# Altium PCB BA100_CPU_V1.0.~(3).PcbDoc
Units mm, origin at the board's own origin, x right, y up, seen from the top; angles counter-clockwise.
Board outline 152.4 x 101.6 mm, 2 copper layers (Top Layer, Bottom Layer); 85 components, 63 nets, 266 pads, 162 vias.
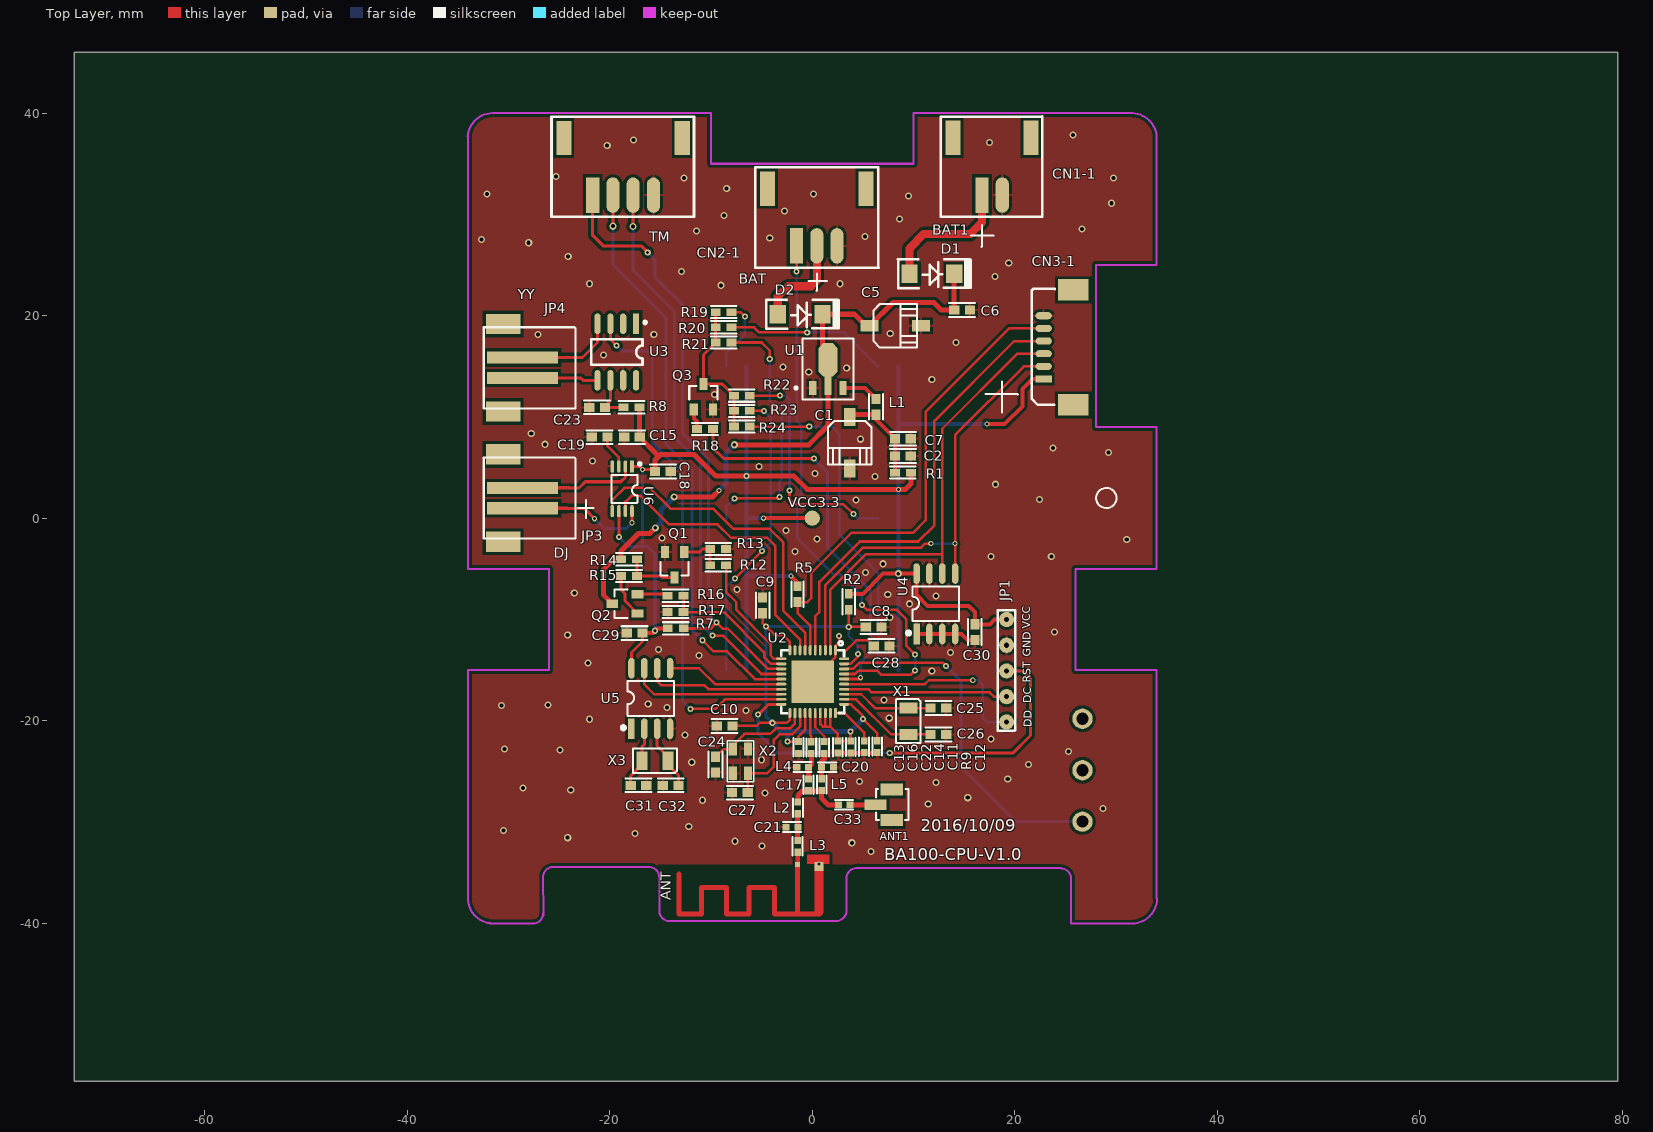
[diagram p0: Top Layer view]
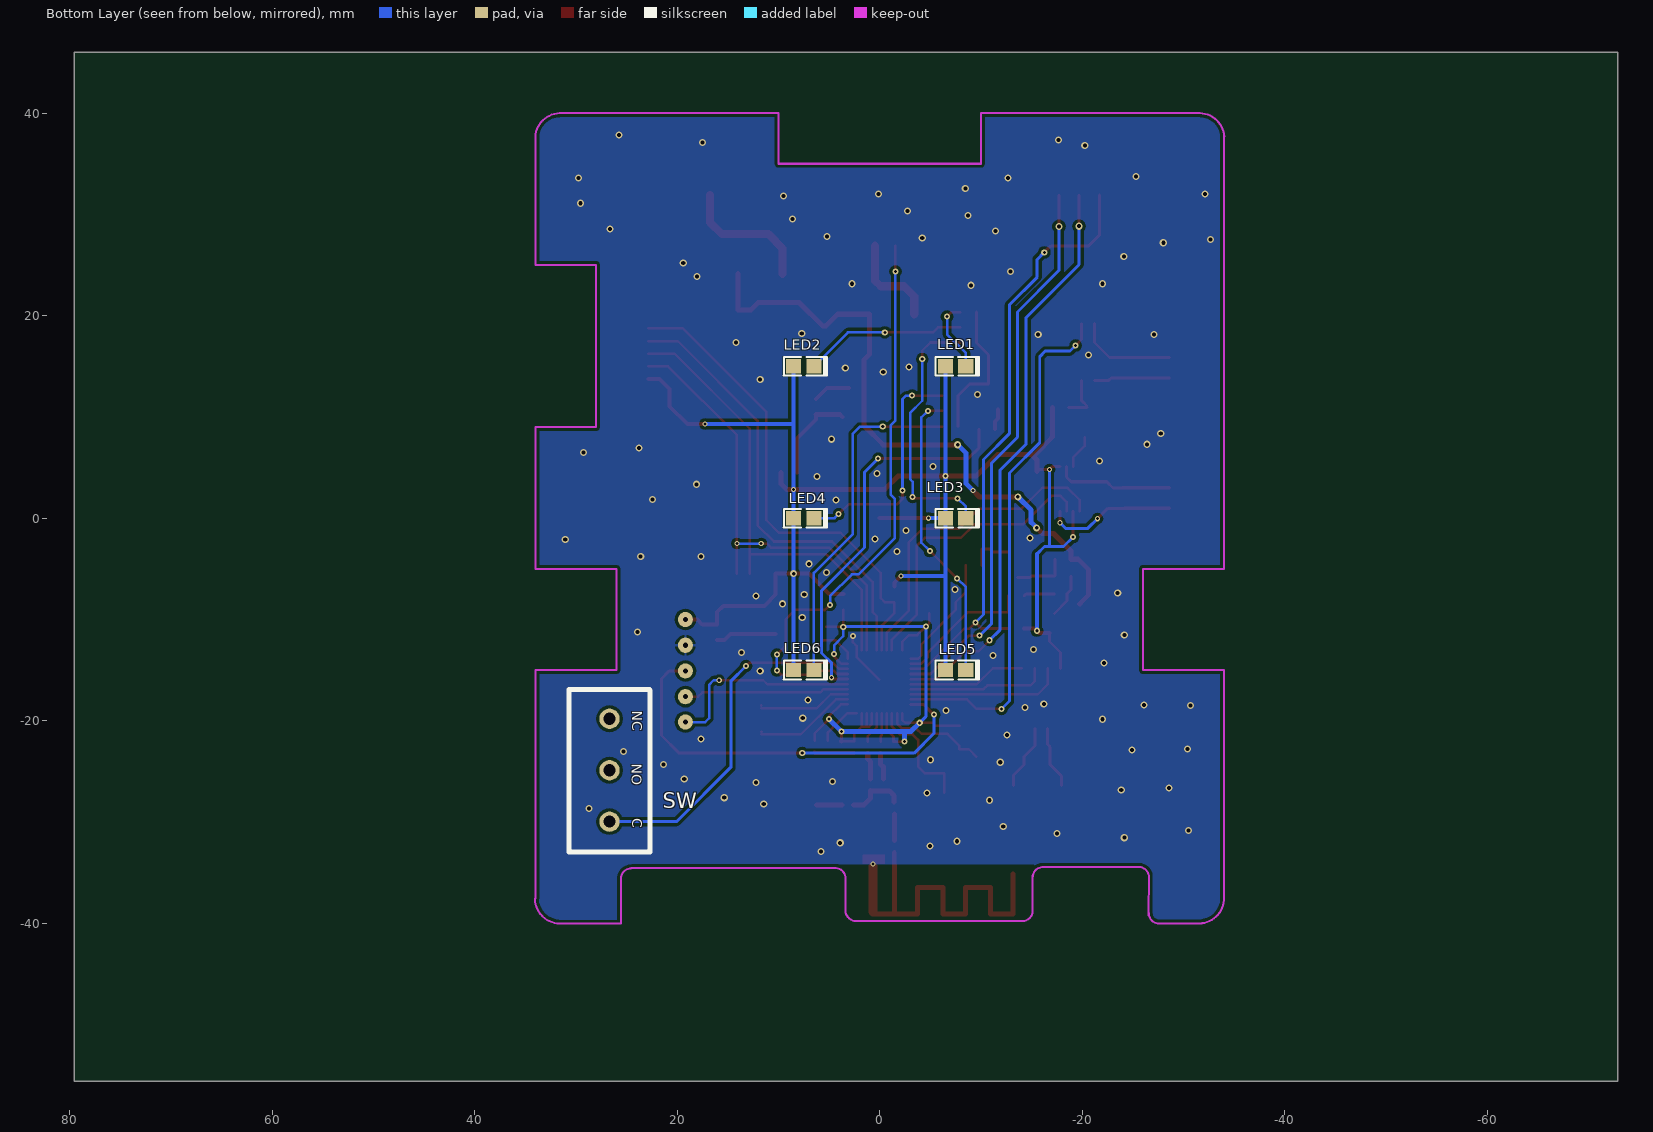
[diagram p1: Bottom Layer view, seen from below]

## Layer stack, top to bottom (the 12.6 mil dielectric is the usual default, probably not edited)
Top Solder: solder mask 0.0102, Solder Resist, Dk 3.5
Top Layer: signal copper 0.0356
Dielectric1: dielectric 0.32, FR-4, Dk 4.8
Bottom Layer: signal copper 0.0356
Bottom Solder: solder mask 0.0102, Solder Resist, Dk 3.5

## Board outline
-72.871,-55.595 79.529,-55.595 79.529,46.005 -72.871,46.005

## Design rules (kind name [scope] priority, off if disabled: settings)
Clearance [All] p1: gap=0.3
ComponentClearance [All] p1 off: gap=0.254 collisioncheckmode=3 verticalgap=0.254 showdistances=FALSE
FabricationTestPointUsage TestPointUsage [All] p1: valid=0 allowmultiple=FALSE
FabricationTestpoint Testpoint [All] p1: side=3 testpointundercomponent=TRUE minsize=1.016 maxsize=2.54 preferedsize=1.524 minholesize=0 maxholesize=1.016 preferedholesize=0.813 testpointgrid=0.025 allowsidetop=TRUE allowsidebottom=TRUE usegrid=TRUE gridtolerance=0
Height [All] p1 off: minheight=0 maxheight=25.4 prefheight=12.7
PlaneClearance [All] p1: clearance=0.3
PlaneConnect [All] p1: planeconnectstyle=Relief reliefexpansion=0.508 reliefentries=4 reliefconductorwidth=0.3 reliefairgap=0.3
PolygonConnect PolygonConnect_1 [IsVia] p1: connectstyle=Direct reliefconductorwidth=0.254 reliefentries=4 polygonreliefangle="90 Angle" airgapwidth=0.254
PolygonConnect [All] p2: connectstyle=Relief reliefconductorwidth=0.254 reliefentries=4 polygonreliefangle="90 Angle" airgapwidth=0.254
RoutingVias [All] p1: holewidth=0.4 width=0.7 viastyle="Through Hole" minholewidth=0.3 minwidth=0.5 maxholewidth=0.7 maxwidth=1.2
SolderMaskExpansion [All] p1: expansion=0.102
UnpouredPolygon [All] p1: allowunpoured=FALSE
Width [All] p1: maxlimit=1 minlimit=0.1 preferedwidth=0.3 minimp=50.000000 maximp=50.000000 favimp=50.000000
23 further rules are at their usual default settings.

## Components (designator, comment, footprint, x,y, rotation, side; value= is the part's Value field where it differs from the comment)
ANT "ANT" ANT -1.451,-34.185 r180 top
ANT1 "ANT" IPEX 6.25,-28.3 r180 top
C1 "10uf/16V,electro" ECAP_10U_4.3*4.3 3.7,7.45 r270 top
C2 "0.1uf" PC7-*****-KO-0A_0603_TDK 8.95,6.15 r180 top
C5 "10uf/16V,electro" ECAP_10U_4.3*4.3 8.2,19 r0 top
C6 "0.1uf" PC5-*****-**-0A_0603_TDK 14.8,20.55 r180 top
C7 "2.2uf" PC5-*****-**-0A_0603_TDK 8.95,7.85 r0 top
C8 "1uf" PC5-*****-**-0A_0603_TDK 6.05,-10.741 r0 top
C9 "0.1uf" PC7-*****-KO-0A_0603_TDK -4.9,-8.6 r90 top
C10 "0.1uf" PC5-*****-**-0A_0603_TDK -8.661,-20.515 r180 top
C11 "0.1uf" PC7-*****-KQA0A_0402_YAGEO 3.789,-22.596 r270 top
C12 "0.1uf" PC7-*****-KQA0A_0402_YAGEO 6.419,-22.555 r270 top
C13 "0.1uf" PC7-*****-KQA0A_0402_YAGEO -1.361,-22.635 r270 top
C14 "220pf" PC7-*****-KQA0A_0402_YAGEO 2.52,-22.596 r90 top
C15 "1uf" PC5-*****-**-0A_0603_TDK -17.8,8 r0 top
C16 "18p" PC7-*****-KQA0A_0402_YAGEO -0.091,-22.655 r270 top
C17 "1p" PC7-*****-KQA0A_0402_YAGEO -0.371,-26.335 r270 top
C18 "0.1uf" PC5-*****-**-0A_0603_TDK -14.75,4.6 r180 top
C19 "1uf" PC5-*****-**-0A_0603_TDK -21,8 r0 top
C20 "1p" PC7-*****-KQA0A_0402_YAGEO 1.5,-24.6 r0 top
C21 "1p" PC7-*****-KQA0A_0402_YAGEO -2,-30.5 r0 top
C22 "18p" PC7-*****-KQA0A_0402_YAGEO 1.179,-22.645 r270 top
C23 "1uf" PC5-*****-**-0A_0603_TDK -21.25,10.95 r180 top
C24 "27p" PC7-*****-KO-0A_0603_TDK -9.551,-24.335 r90 top
C25 "15P" PC5-*****-**-0A_0603_TDK 12.45,-18.745 r180 top
C26 "15P" PC7-*****-KO-0A_0603_TDK 12.45,-21.35 r180 top
C27 "27p" PC7-*****-KO-0A_0603_TDK -7.15,-27.1 r0 top
C28 "1uf" PC5-*****-**-0A_0603_TDK 6.85,-12.6 r180 top
C29 "0.1uf" PC7-*****-KO-0A_0603_TDK -17.55,-11.35 r180 top
C30 "0.1uf" PC5-*****-**-0A_0603_TDK 16.05,-11.25 r90 top
C31 "15P" PC7-*****-KO-0A_0603_TDK -17.161,-26.375 r0 top
C32 "15P" PC7-*****-KO-0A_0603_TDK -13.981,-26.375 r180 top
C33 "20P" PC7-*****-KQA0A_0402_YAGEO 3.15,-28.3 r0 top
CN1-1 "CN1" PH2.0-2PIN-SMT 16.75,31.9 r0 top
CN2-1 "CN2" PH2.0-3PIN-SMT -1.55,26.9 r0 top
CN3-1 "touch" PH1.25-6PIN-SMT 22.849,13.745 r90 top
D1 "SS12" SS12-DIDEO 9.6,24.15 r0 top
D2 "SS12" SS12-DIDEO -3.4,20.15 r0 top
JP1 "debugger" ISCP-5PIN 19.189,-10.005 r270 top
JP3 "SIP2" PH2.0-2PIN-LSMT1 -28.611,1.985 r270 top
JP4 "SIP2" PH2.0-2PIN-LSMT1 -28.611,14.855 r270 top
L1 "BLM18HG102SN1" PC7-*****-KO-0A_0603_TDK 6.3,11 r270 top
L2 "1nH" PC5-*****-**-0A_0402_TDK -1.421,-28.6 r270 top
L3 "3nH" PC5-*****-**-0A_0402_TDK -1.451,-32.405 r270 top
L4 "2nH" PC5-*****-**-0A_0402_TDK -0.951,-24.575 r0 top
L5 "2nH" PC5-*****-**-0A_0402_TDK 0.929,-26.305 r270 top
LED1 "MA2X335" LED-0805 -7.5,15 r180 bottom locked
LED2 "MA2X335" LED-0805 7.5,15 r180 bottom locked
LED3 "MA2X335" LED-0805 -7.5,0 r180 bottom locked
LED4 "MA2X335" LED-0805 7.5,0 r180 bottom locked
LED5 "MA2X335" LED-0805 -7.5,-15 r180 bottom locked
LED6 "MA2X335" LED-0805 7.5,-15 r180 bottom locked
Q1 "BC847B" PTR-C0025-00-2A_2SC1623 -13.6,-4.6 r180 top
Q2 "BC857B" PTR-C0025-00-2A_2SC1623 -18.5,-8.45 r90 top
Q3 "SS8050" PTR-C0025-00-2A_2SC1623 -10.75,12 r0 top
R1 "0ohm" PRC-*****-AM-0A_0603 8.95,4.5 r0 top
R2 "0ohm" PRC-*****-AM-0A_0603 3.6,-8.25 r90 top
R5 "10k" PRC-*****-AM-0A_0603 -1.45,-7.5 r270 top
R7 "10k" PRC-*****-AM-0A_0603 -13.481,-10.875 r0 top
R8 "0ohm" PRC-*****-AM-0A_0603 -17.85,10.95 r0 top
R9 "56k" PRC-*****-BM-0A_0402 5.112,-22.569 r270 top
R12 "4.7K" PRC-*****-AM-0A_0603 -9.3,-4.65 r180 top
R13 "100K" PRC-*****-AM-0A_0603 -9.3,-3.05 r180 top
R14 "47K" PRC-*****-AM-0A_0603 -18.1,-4.05 r180 top
R15 "30K" PRC-*****-AM-0A_0603 -18.1,-5.7 r180 top
R16 "75K" PRC-*****-AM-0A_0603 -13.5,-7.65 r180 top
R17 "20K" PRC-*****-AM-0A_0603 -13.501,-9.265 r0 top
R18 "2.7K" PRC-*****-AM-0A_0603 -10.6,8.8 r180 top
R19 "560" PRC-*****-AM-0A_0603 -8.75,20.35 r180 top
R20 "560" PRC-*****-AM-0A_0603 -8.75,18.85 r180 top
R21 "560" PRC-*****-AM-0A_0603 -8.75,17.35 r180 top
R22 "560" PRC-*****-AM-0A_0603 -6.95,12.1 r180 top
R23 "560" PRC-*****-AM-0A_0603 -6.95,10.6 r180 top
R24 "560" PRC-*****-AM-0A_0603 -6.95,9.05 r180 top
SW "SW-weidong" SW-weidong 26.679,-24.885 r90 bottom
TM "TM" PH2.0-4PIN-SMT -21.681,31.905 r0 top (schematic designator JP2)
U1 "HT7333" SOT89 1.55,14.25 r0 top
U2 "CC2541" CC2530_QFN40 2.3,-13.05 r270 top
U3 "NVC080C" SOP-8 -17.4,19.2 r270 top
U4 "AT24C64N" PIC-00570-40-2A_93LC46B 12.2,-8.45 r90 top
U5 "DS1302Z" PIC-00570-40-2A_93LC46B -15.95,-17.8 r90 top
U6 "PT5102" PT5102 -17.8,5.1 r270 top
X1 "32.768KHZ,F=12.5P" FC-135 9.489,-20.045 r270 top
X2 "CY_3225" CY_3225 -7.421,-25.095 r90 top
X3 "32.768KHZ,F=6P" FC-135 -15.531,-23.955 r180 top

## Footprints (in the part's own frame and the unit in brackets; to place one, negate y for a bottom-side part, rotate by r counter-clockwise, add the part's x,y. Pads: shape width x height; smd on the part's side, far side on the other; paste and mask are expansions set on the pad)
ANT [mm]
  rect 0.5x0.5 smd: 1(0,0)
  rect 0.9x0.9 smd: 2(-2.1,0.2)
  Top Layer lines w0.5: 11.7,0.96 11.7,4.9 9.5,4.9 9.5,2.26 7,2.26 7,4.9 4.8,4.9 4.8,2.26 2.3,2.26 2.3,4.9 0,4.9 ; 0,0 0,4.9 ; -2.26,4.79 -2.21,4.84 -2.15,4.9 0,4.9
  Top Layer lines w0.9: -2.1,4.65 -2.1,0.2
CC2530_QFN40 [mm]
  oval 1x0.28 smd: 1(-0.011,-0.009) 2(-0.011,-0.509) 3(-0.011,-1.009) 4(-0.011,-1.509) 5(-0.011,-2.009) 6(-0.011,-2.509) 7(-0.011,-3.009) 8(-0.011,-3.509) 9(-0.011,-4.009) 10(-0.011,-4.509) 21(6.189,-4.509) 22(6.189,-4.009) 23(6.189,-3.509) 24(6.189,-3.009) 25(6.189,-2.509) 26(6.189,-2.009) 27(6.189,-1.509) 28(6.189,-1.009) 29(6.189,-0.509) 30(6.189,-0.009)
  oval 0.28x1 smd: 11(0.832,-5.359) 12(1.332,-5.359) 13(1.832,-5.359) 14(2.332,-5.359) 15(2.832,-5.359) 16(3.332,-5.359) 17(3.832,-5.359) 18(4.332,-5.359) 19(4.832,-5.359) 20(5.332,-5.359) 31(5.332,0.841) 32(4.832,0.841) 33(4.332,0.841) 34(3.832,0.841) 35(3.332,0.841) 36(2.832,0.841) 37(2.332,0.841) 38(1.832,0.841) 39(1.332,0.841) 40(0.832,0.841)
  rect 4.2x4.2 smd: 41(3.089,-2.259)
  silkscreen extent -0.91,-5.37 6.21,0.85
CY_3225 [mm]
  round 0.5 on Top Overlay: 0(-0.64,-2.06)
  rect 1.3x0.8 smd: 1(-0.095,-1.07) 2(2.293,-1.07) 3(2.293,0.428) 4(-0.095,0.428)
  silkscreen extent -0.91,-1.63 3.11,0.99
ECAP_10U_4.3*4.3 [mm]
  rect 1.8x1.1 smd: 1(2.54,0) 2(-2.54,0)
  silkscreen extent -2.15,-2.15 2.15,2.15
FC-135 [mm]
  rect 1.1x1.8 smd: 1(-1.3,0) 2(1.3,0)
  silkscreen extent -2.17,-1.2 2.15,1.19
IPEX [mm]
  rect 2.2x1 smd: 1(0,0)
  rect 2.2x1.2 smd: 2(-1.6,-1.5) 3(-1.6,1.49)
  silkscreen extent -3.24,-1.56 -0.05,1.51
ISCP-5PIN [mm]
  round 1.5 hole 0.5: 1(0,0) 2(2.54,0) 3(5.07,0) 4(7.62,0) 5(10.12,0)
  silkscreen extent -0.93,-0.89 11,0.84
LED-0805 [mm]
  rect 1.5x1.4 smd: A(-1,0) C(1,0)
  silkscreen extent -1.98,-0.93 2.28,0.93
PC5-*****-**-0A_0402_TDK [mm] "0402"
  rect 0.7x0.65 smd: 1(-0.58,0) 2(0.58,0)
  silkscreen extent -0.91,-0.48 0.89,0.48
PC5-*****-**-0A_0603_TDK [mm] "0603"
  rect 1.016x0.9 smd: 1(-0.775,0) 2(0.776,0)
  silkscreen extent -1.28,-0.68 1.28,0.68
PC7-*****-KO-0A_0603_TDK [mm] "0603"
  rect 1.016x0.9 smd: 1(-0.776,0) 2(0.776,0)
  silkscreen extent -1.28,-0.68 1.28,0.68
PC7-*****-KQA0A_0402_YAGEO [mm] "0402"
  rect 0.7x0.65 smd: 1(-0.58,0) 2(0.58,0)
  silkscreen extent -0.91,-0.48 0.89,0.48
PH1.25-6PIN-SMT [mm]
  rect 0.7x1.6 smd: 1(0,0)
  oval 0.7x1.6 smd: 2(1.25,0) 3(2.5,0) 4(3.75,0) 5(5,0) 6(6.25,0)
  rect 2.1x3 smd: 7(-2.55,-2.91) 8(8.8,-2.91)
  silkscreen extent -2.54,-1.11 8.89,1.18
PH2.0-2PIN-LSMT1 [mm]
  rect 1.2x7 smd: 1(-1.005,0) 2(1.005,0)
  rect 2x3.4 smd: 3(-4.318,-1.905) 4(4.318,-1.905)
  silkscreen extent -4,-3.84 4,5.24
PH2.0-2PIN-SMT [mm]
  rect 1.3x3.5 smd: 1(0.01,0.01)
  oval 1.3x3.5 smd: 2(2.01,0.01)
  rect 1.5x3.4 smd: 3(-2.85,5.65) 4(4.85,5.65)
  silkscreen extent -4.06,-2.15 5.98,7.8
PH2.0-3PIN-SMT [mm]
  rect 1.3x3.5 smd: 1(0,0)
  oval 1.3x3.5 smd: 2(2,0) 3(3.99,-0.01)
  rect 1.5x3.4 smd: 4(-2.86,5.64) 5(6.85,5.64)
  silkscreen extent -4.07,-2.17 8.1,7.75
PH2.0-4PIN-SMT [mm]
  rect 1.3x3.5 smd: 1(0,0)
  oval 1.3x3.5 smd: 2(2,0) 3(3.99,-0.01) 4(6,-0.01)
  rect 1.5x3.4 smd: 5(-2.85,5.64) 6(8.85,5.64)
  silkscreen extent -4.07,-2.16 10,7.75
PIC-00570-40-2A_93LC46B [mil] "SOIC-8"
  rect 80x25 smd: 1(-117.5,75)
  oval 80x25 smd: 2(-117.5,25) 3(-117.5,-25) 4(-117.5,-75) 5(117.5,-75) 6(117.5,-25) 7(117.5,25) 8(117.5,75)
  silkscreen extent -119,-90 67,111
PRC-*****-AM-0A_0603 [mm] "0603"
  rect 0.966x0.762 smd: 1(-0.785,0) 2(0.785,0)
  silkscreen extent -1.26,-0.6 1.27,0.6
PRC-*****-BM-0A_0402 [mm] "0402"
  rect 0.7x0.65 smd: 1(-0.58,0) 2(0.58,0)
  silkscreen extent -0.91,-0.48 0.89,0.48
PT5102 [mm]
  rect 1.2x0.35 smd: 1(0,0)
  oval 1.2x0.35 smd: 2(-0.006,-0.65) 3(-0.006,-1.3) 4(-0.006,-1.95) 5(4.4,-1.95) 6(4.4,-1.3) 7(4.4,-0.65) 8(4.4,0)
  silkscreen extent -0.38,-2.03 3.58,0.89
PTR-C0025-00-2A_2SC1623 [mm]
  rect 0.816x1.174 smd: B(-0.95,-1.25) C(0,1.251) E(0.95,-1.25)
  silkscreen extent -1.4,-0.26 1.4,1.04
SOP-8 [mil]
  rect 80x24 smd: 1(0,0)
  oval 80x24 smd: 2(0,-50) 3(0,-100) 4(0,-150) 5(220,-150) 6(220,-100) 7(220,-50) 8(220,0)
  silkscreen extent -10,-175 160,40
SOT89 [mm] "SOT-89; Body 4.6 x 4.25 mm, inc. leads (LxW max)"
  oct 1.9x3.3 smd: 0(0,1.388)
  rect 0.7x1.35 smd: 1(-1.5,-1.388) 3(1.5,-1.388)
  rect 0.7x1.8 smd: 2(0,-1.162)
  silkscreen extent -3.27,-2.51 2.5,3.49
SS12-DIDEO [mm]
  rect 1.6x1.8 smd: 1(4.41,-0.01) 2(-0.01,-0.01)
  silkscreen extent -1.14,-1.43 6.03,1.44
SW-weidong [mm]
  round 2 hole 1.2: 1(-5.08,0) 2(0,0) 3(5.08,0)
  silkscreen extent -8.08,-4.01 7.95,4.01

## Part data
C1 C2 C5 C6 C7 C8 C9 C10 C11 C12 C13 C14 C15 C16 C17 C18 C19 C20 C21 C22 C23 C24 C25 C26 C27 C28 C29 C30 C31 C32 C33: library part PC7_0402_YAGEO, "PC7-*****-KQA0A"
CN1-1 JP3 JP4: library part CON2, "Connector"
CN2-1: library part JP1_E524.03
CN3-1: library part CON6
D1 D2: library part PDD_SD101CWS, "PDD-00330-00-2A"
JP1: library part CON5
L1 L2 L3 L4 L5: library part PWL_18nH, "PWL-00195-00-20"
LED1 LED2 LED3 LED4 LED5 LED6: library part PDD_MA2X335, "LED"
Q1: library part PTR_2SC3356, "PTR-C0028-00-2A"
Q2: library part PTR-PNP
Q3: library part PTR_2SC5344SF-Y, "PTR-C0230-00-20**"
R1 R2 R5 R7 R8 R9 R12 R13 R14 R15 R16 R17 R18: library part PRC_0603, "PRC-*****-AM-0A_0603"
R19 R20 R21 R22 R23 R24: library part RES
TM: library part "HDR1X4 ***"
U1: library part LM117K
U3: library part NV040C
U5: library part DS1302
U6: library part Component_1_1
X1: library part CRYSTAL, "Crystal"
X3: library part PTR_16MHZ, "PTR-X0320-20-2A"

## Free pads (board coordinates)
  round 1.5 smd: 0(0,0)

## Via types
v1: diameter 0.7, hole 0.4, Top Layer to Bottom Layer, 108 vias
v2: diameter 0.6, hole 0.3, Top Layer to Bottom Layer, 37 vias
v3: diameter 0.508, hole 0.3, Top Layer to Bottom Layer, 13 vias
v4: diameter 0.7, hole 0.35, Top Layer to Bottom Layer, 4 vias

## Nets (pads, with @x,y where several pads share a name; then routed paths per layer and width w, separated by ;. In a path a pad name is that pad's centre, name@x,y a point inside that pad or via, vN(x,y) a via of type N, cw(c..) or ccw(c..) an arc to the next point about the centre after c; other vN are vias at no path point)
AD: R16.1 R17.2 U2.12 | length 13.6
  Top Layer w0.25: R16.1@-12.696,-7.665 -12.696,-9.245 R17.2 -8.735,-9.265 -4.75,-13.25 -4.75,-13.7 -4.068,-14.382 U2.12
DC: JP1.4 U2.34 | length 16.4
  Top Layer w0.25: U2.34 5.532,-16.882 5.85,-17.2 17.5,-17.2 17.925,-17.625 JP1.4
DD: JP1.5 U2.35 | length 19.8
  Top Layer w0.25: U2.35 11.118,-16.382 11.5,-16 v3(15.85,-16)
  Bottom Layer w0.25: v3(15.85,-16) 16.4,-16 16.85,-16.45 16.85,-19.75 17.225,-20.125 JP1.5
DJ1: U2.7 U6.5 | length 32.3
  Top Layer w0.25: U6.5 -19.75,1.8 -18.55,3 -16.05,3 -14,0.95 -9.8,0.95 -7.8,-1.05 -4.2,-1.05 -2.85,-2.4 -2.85,-9.15 -0.709,-11.291 U2.7
DJ2: U2.8 U6.7 | length 29.3
  Top Layer w0.25: U6.7 -18.45,1.6 -17.85,2.2 -16.95,2.2 -14.15,-0.6 -9.35,-0.6 -8,-1.95 -4.45,-1.95 -3.65,-2.75 -3.65,-9.55 -1.209,-11.991 U2.8
GND: C1.1 C2.1 C5.1 C6.1 C7.2 C8.2 C9.2 C10.2 C11.2 C12.2 C13.2 C14.1 C15.1 C18.1 C19.1 C20.2 C21.1 C23.2 C24.1 C25.1 C26.1 C27.1 C28.1 C29.2 C30.1 C31.2 C32.2 CN1-1.2 CN2-1.3 CN3-1.6 JP1.2 L4.1 Q1.E Q3.E R9.2 R13.1 R17.1 TM.4 U1.1 U2.1 U2.41 U3.7 U4.1 U4.2 U4.3 U4.4 U4.7 U5.4 U6.4 X2.2 X2.4 | length 15.3
  Top Layer w0.25: U2.41@0.041,-15.959 2.291,-13.709 U2.1 2.291,-12.609 2.65,-12.25 v2(2.65,-11.65)
  Top Layer w0.4: C14.1 6.378,-23.176 C12.2 ; U4.1 U4.2 U4.3 U4.4 14.735,-11.435 15.325,-12.025 C30.1
  other v1: 5.8,-32.9 -4.95,-32.35 3.9,-32.05 -7.65,-31.9 -24.15,-31.55 -17.5,-31.15 -30.5,-30.85 -12.2,-30.45 28.7,-28.65 11.45,-28.2 -10.85,-27.85 15.35,-27.6 -4.65,-27.15 -23.85,-26.85 -28.55,-26.65 12.2,-26.1 4.65,-26 19.3,-25.75 21.35,-24.3 -11.9,-24.1 -5,-23.85 25.3,-23.05 -24.9,-22.9 -30.4,-22.8 17.65,-21.8 -12.55,-21.4 -22,-19.85 7.6,-19.75 -6.55,-19 -14.35,-18.7 -30.7,-18.5 -26.1,-18.45 -16.2,-18.35 7.1,-17.95 11.8,-15.1 -22.15,-14.3 -11.2,-13.55 13.65,-13.25 -15.2,-12.95 -24.15,-11.55 23.9,-11.25 7.65,-9.8 9.6,-8.45 12.2,-7.7 7.45,-7.55 -23.5,-7.4 -7.45,-7.05 5.25,-5.35 7,-4.5 17.65,-3.8 23.6,-3.8 -1.7,-3.3 31.05,-2.1 0.45,-2.05 -14.85,-1.95 -2.6,-1.2 4.3,1.8 22.45,1.85 18.1,3.35 6.2,4.1 0.25,4.4 -5.25,5.1 -21.7,5.65 29.25,6.5 23.75,6.95 -26.4,7.3 4.75,7.8 -27.75,8.35 -9.65,12.2 11.8,13.7 -0.35,14.45 3.4,14.85 -2.9,14.95 -20.6,16.1 14.2,17.35 -27.1,18.15 -15.65,18.15 7.7,18.25 -9,23 -22,23.15 2.75,23.15 18.05,23.85 -12.9,24.35 19.4,25.2 -24.1,25.85 -28,27.2 -32.65,27.5 -4.2,27.65 5.2,27.8 -11.45,28.35 26.65,28.55 8.6,29.55 -8.7,29.9 -2.75,30.35 29.55,31.1 9.5,31.8 -32.1,32 0.1,32 -8.45,32.55 -12.65,33.6 29.75,33.6 -25.3,33.75 -20.25,36.8 17.5,37.1 -17.65,37.35 25.75,37.85
  other v3: 0.65,-34.15
HI: CN3-1.5 R5.2 U2.6 | length 48.4
  Top Layer w0.25: R5.2@-1.45,-8.335 -1.45,-9.35 -0.209,-10.591 U2.6 ; R5.2 -0.485,-8.285 -0.1,-7.9 -0.1,-5.4 3.85,-1.45 9.95,-1.45 11.2,-0.2 11.2,10.5 19.445,18.745 CN3-1.5
LED_BACK: R18.1 U2.36 | length 38.3
  Top Layer w0.3: R18.1 -9.815,6.965 -8.75,5.9 v2(0.15,5.9) ; U2.36 4.618,-15.882 v3(4.75,-15.75)
  Bottom Layer w0.3: v2(0.15,5.9) 1.5,4.55 1.5,-2.9 5.75,-7.15 5.75,-13.3 4.75,-14.3 v3(4.75,-15.75)
NetANT1_1: ANT1.1 C33.2 | length 2.5
  Top Layer w0.5: C33.2 ANT1.1
NetANT_1: ANT.1 L3.2 | length 1.2
  Top Layer w0.45: ANT.1 L3.2
NetC1_2: C1.2 C2.2 C7.1 L1.2 R1.1 | length 9.2
  Top Layer w0.3: R1.1 R1.1@8.175,4.51
  Top Layer w0.4: C1.2 C1.2@3.935,10.225 ; L1.2 6.3,9.725 C7.1 R1.1@8.175,4.51
  Top Layer w0.5: C1.2@3.935,10.225 L1.2
NetC8_1: C8.1 C9.1 C10.1 C11.1 C12.1 C13.1 C14.2 R2.1 U2.10 U2.21 U2.24 U2.27 U2.28 U2.29 U2.31 U2.39 | length 67.4
  Top Layer w0.25: C10.1 -5.515,-20.515 -5.2,-20.2 v2(-3.95,-20.2) -2.5,-20.2 -2.209,-19.909 U2.21 ; C9.1 -4.9,-10.35 v2(-4.55,-10.7) -3.7,-11.55 -2.9,-11.55 -2.209,-12.241 U2.10 ; v2(-2.45,-22.055) C13.1 ; C13.1@-1.459,-21.956 C13.1 ; U2.24 -0.709,-20.909 -1.361,-21.561 C13.1 ; U2.27 0.791,-20.341 1.041,-20.591 1.291,-20.591 ; U2.28 1.291,-20.591 ; U2.29 1.791,-20.509 1.709,-20.591 ; U2.31 3.832,-18.382 5,-19.55 v2(5,-19.839) 6.419,-21.258 C12.1 ; U2.39 3.768,-14.382 4.5,-13.65 v2(4.5,-13.4) ; R2.1 v2(3.6,-10.741) C8.1 ; C11.1 C14.2 2.52,-21.32 1.791,-20.591 1.709,-20.591 ; 1.291,-20.591 1.709,-20.591
  Top Layer w0.3: C11.1 v2(3.789,-21.05)
  Bottom Layer w0.25: v2(3.6,-10.741) 3.6,-11.65 4.5,-12.55 v2(4.5,-13.4)
  Bottom Layer w0.3: v2(-3.95,-20.2) -4.55,-19.6 v2(-4.55,-10.7) 3.558,-10.7 v2(3.6,-10.741)
  Bottom Layer w0.5: v2(-3.95,-20.2) -3.1,-21.05 v2(3.789,-21.05) v2(5,-19.839) ; v2(-2.45,-22.055) -2.45,-21.1
NetC16_1: C16.1 U2.25 | length 2.9
  Top Layer w0.25: U2.25 -0.209,-21.432 -0.091,-21.55 C16.1
NetC16_2: C16.2 C17.1 L4.2 | length 2.6
  Top Layer w0.5: C17.1 L4.2 -0.091,-24.295 C16.2
NetC17_2: C17.2 C33.1 L2.1 L5.2 | length 5.9
  Top Layer w0.5: L2.1 -1.421,-27.371 -0.965,-26.915 C17.2 0.899,-26.915 L5.2 0.929,-27.679 1.55,-28.3 C33.1
NetC19_2: C19.2 U6.3 | length 3.4
  Top Layer w0.25: C19.2 -20.224,7.124 -19.1,6 U6.3
NetC20_1: C20.1 C22.2 L5.1 | length 2.6
  Top Layer w0.5: L5.1 0.92,-25.716 C20.1 0.92,-24.03 1.179,-23.771 C22.2
NetC21_2: C21.2 L2.2 L3.1 | length 2.6
  Top Layer w0.5: L3.1 L2.2@-1.451,-29.21
NetC22_1: C22.1 U2.26 | length 3.2
  Top Layer w0.25: U2.26 0.291,-20.641 1.179,-21.529 C22.1
NetC23_1: C23.1 R8.1 U3.6 | length 4.6
  Top Layer w0.3: C23.1 R8.1 ; C23.1@-20.475,11.075 -19.94,11.61 U3.6
NetC24_2: C24.2 U2.22 X2.3 | length 10.4
  Top Layer w0.25: C24.2 -8.794,-22.802 X2.3 -7.849,-22.449 -6.7,-21.3 -4.15,-21.3 -3.6,-20.75 -2.2,-20.75 -1.709,-20.259 U2.22
NetC25_2: C25.2 U2.33 X1.1 | length 9.1
  Top Layer w0.25: U2.33 4.832,-17.382 6.195,-18.745 X1.1 C25.2
NetC26_2: C26.2 U2.32 X1.2 | length 10
  Top Layer w0.25: U2.32 4.332,-17.882 7.795,-21.345 X1.2 11.669,-21.345 C26.2 ; C26.2@11.669,-21.095 C26.2@11.675,-21.1
NetC27_2: C27.2 U2.23 X2.1 | length 11.8
  Top Layer w0.25: C27.2 -6.351,-27.076 X2.1 -4.49,-25.19 -3.8,-24.5 -3.8,-21.9 -3.25,-21.35 -2,-21.35 -1.209,-20.559 U2.23
NetC28_2: C28.2 U2.40 | length 4.3
  Top Layer w0.25: U2.40 3.141,-13.259 4.35,-12.05 5.524,-12.05 C28.2
NetC31_1: C31.1 U5.2 X3.2 | length 6.2
  Top Layer w0.3: C31.1 -17.936,-25.436 -16.831,-24.331 X3.2 -16.831,-22.581 -16.585,-22.335 U5.2
NetC32_1: C32.1 U5.3 X3.1 | length 6.5
  Top Layer w0.3: U5.3 -15.315,-22.485 -14.231,-23.569 X3.1 -14.231,-24.369 -13.205,-25.395 C32.1
NetCN1-1_1: CN1-1.1 D1.2 | length 13.4
  Top Layer w0.8: D1.2 9.59,26.64 11,28.05 15.6,28.05 16.76,29.21 CN1-1.1
NetCN2-1_2: CN2-1.2 D2.2 | length 9.7
  Top Layer w0.8: D2.2 -3.41,21.89 -2.4,22.9 -0.1,22.9 0.45,23.45 CN2-1.2
NetJP4_1: JP4.1 U3.4 | length 9.9
  Top Layer w0.3: JP4.1 -22.69,15.86 -21.21,17.34 U3.4
NetJP4_2: JP4.2 U3.5 | length 7.5
  Top Layer w0.3: JP4.2 -22.85,13.85 -22.612,13.612 U3.5
NetL1_1: L1.1 U1.3 | length 3.7
  Top Layer w0.4: U1.3 5.213,12.862 L1.1
NetLED1_C: LED1.C R19.1 | length 7.2
  Top Layer w0.25: R19.1 -7.1,20.35 v2(-6.65,19.9)
  Bottom Layer w0.25: LED1.C -8.5,16.3 -6.65,18.15 v2(-6.65,19.9)
NetLED2_C: LED2.C R20.1 | length 16.1
  Top Layer w0.25: R20.1 -5.75,18.85 -5.25,18.35 v2(-0.5,18.35)
  Bottom Layer w0.25: v2(-0.5,18.35) 3.15,18.35 LED2.C
NetLED3_C: LED3.C R21.1 | length 25.9
  Top Layer w0.25: R21.1 -5,17.35 -4.2,16.55 v2(-4.2,15.7) ; v2(-7.7,1.95) -3.4,1.95 v2(-3.25,2.1)
  Bottom Layer w0.25: LED3.C -8.5,1.15 v2(-7.7,1.95) ; v2(-4.2,15.7) -4.2,11.6 -3,10.4 -3,3.85 -3.25,3.6 v2(-3.25,2.1)
NetLED4_C: LED4.C R22.1 | length 23.4
  Top Layer w0.25: R22.1 v2(-3.2,12.1) ; v2(-2.25,2.75) -2.25,1.9 -1.75,1.4 3.05,1.4 v2(4.05,0.4)
  Bottom Layer w0.25: v2(-3.2,12.1) -2.6,12.1 -2.25,11.75 v2(-2.25,2.75) ; v2(4.05,0.4) 4.45,0 LED4.C
NetLED5_C: LED5.C R23.1 | length 29.1
  Top Layer w0.25: v2(-7.65,-5.95) v2(-4.95,-3.25) ; R23.1 v2(-4.75,10.6)
  Bottom Layer w0.25: LED5.C -8.5,-6.8 v2(-7.65,-5.95) ; v2(-4.95,-3.25) -4.1,-2.4 -4.1,9.95 v2(-4.75,10.6)
NetLED6_C: LED6.C R24.1 | length 34
  Top Layer w0.25: R24.1 v2(-0.3,9.05)
  Bottom Layer w0.25: v2(-0.3,9.05) 1.95,9.05 2.65,8.35 2.65,-1.55 6.5,-5.4 LED6.C
NetQ1_B: Q1.B R12.2 R13.2 | length 4.3
  Top Layer w0.3: Q1.B -11.15,-3.35 -10.85,-3.05 R13.2 R12.2
NetQ1_C: Q1.C R14.1 R15.1 | length 5.4
  Top Layer w0.3: R14.1 R15.1 -15,-5.7 -14.849,-5.851 Q1.C
NetQ2_B: Q2.B R15.2 | length 4.4
  Top Layer w0.3: R15.2 -18.885,-7.065 -18.5,-7.45 -18.5,-8.15 Q2.B
NetQ2_E: Q2.E R16.2 | length 3.1
  Top Layer w0.3: Q2.E -14.431,-7.5 R16.2@-14.266,-7.665
NetQ3_B: Q3.B R18.2 | length 2.1
  Top Layer w0.4: Q3.B -11.7,9.85 -11.385,9.535 R18.2
NetQ3_C: Q3.C R19.2 R20.2 R21.2 R22.2 R23.2 R24.2 | length 14.1
  Top Layer w0.3: R19.2 R20.2 R21.2 -10.75,16.135 Q3.C -8.886,13.251 R22.2 R23.2 R24.2
NetR9_1: R9.1 U2.30 | length 4.5
  Top Layer w0.25: U2.30 3.201,-19.239 5.112,-21.15 R9.1
O1: JP3.1 U6.2 | length 11.7
  Top Layer w0.3: -24.01,2.99 -23.04,2.99 -22.43,3.6 -18.9,3.6 -18.45,4.05 U6.2
  Top Layer w0.35: JP3.1 -24.01,2.99
O2: JP3.2 U6.8 | length 13
  Top Layer w0.3: -24.18,0.98 -22.53,0.98 v3(-21.5,-0.05) ; v3(-17.8,-0.45) U6.8
  Top Layer w0.35: JP3.2 -24.18,0.98
  Bottom Layer w0.3: v3(-21.5,-0.05) -20.55,-1 -18.35,-1 v3(-17.8,-0.45)
P10: R12.1 U2.11 | length 11.9
  Top Layer w0.25: R12.1 -8.515,-7.285 -7.5,-8.3 -7.5,-9.05 -4.1,-12.45 -4.1,-13.55 -3.768,-13.882 U2.11
P16: U2.38 | length 35.3
  Top Layer w0.25: U2.38 4.018,-14.882 4.65,-14.25 12.85,-14.25 v2(13.2,-14.6)
  Bottom Layer w0.3: v2(13.2,-14.6) 14.7,-16.1 14.7,-24.6 20.065,-29.965 26.679,-29.965
RST: JP1.3 U2.20 | length 41.3
  Top Layer w0.3: v2(-5.35,-19.4) -4.332,-18.382 U2.20 ; v2(7.65,-23.2) 19.8,-23.2 21.55,-21.45 21.55,-15.85 20.775,-15.075 JP1.3
  Bottom Layer w0.3: v2(-5.35,-19.4) -5.35,-21.25 -3.4,-23.2 v2(7.65,-23.2)
RST-S: CN2-1.1 U2.37 | length 56.8
  Top Layer w0.25: v2(-1.55,24.35) CN2-1.1 ; U2.37 4.218,-15.382 4.55,-15.05 6.4,-15.05 6.8,-15.45 9.75,-15.45 v2(10.15,-15.05) ; v2(4.9,-8.55) 5.45,-9.1 5.525,-9.025 8.325,-9.025 9.3,-10 9.3,-12.6 v2(10.15,-13.45)
  Bottom Layer w0.25: v2(-1.55,24.35) -1.55,9.65 -1.1,9.2 -1.1,2.3 -1.5,1.9 -1.5,-1.95 2.1,-5.55 2.75,-5.55 4.9,-7.7 v2(4.9,-8.55) ; v2(10.15,-15.05) v2(10.15,-13.45)
SCL: CN3-1.3 U2.2 U4.6 | length 45.9
  Top Layer w0.25: U2.2 1.791,-7.059 5.3,-3.55 12.835,-3.55 ; U4.6 12.835,-3.55 ; CN3-1.3 20.245,16.245 12.835,8.835 12.835,-3.55
SDA: CN3-1.2 U2.3 U4.5 | length 46.2
  Top Layer w0.25: U2.3 1.291,-6.609 5,-2.9 10.75,-2.9 11.15,-2.5 v3(11.7,-2.5) ; U4.5 v3(14.105,-2.5) 14.105,8.205 20.895,14.995 CN3-1.2
  Bottom Layer w0.25: v3(11.7,-2.5) v3(14.105,-2.5)
T-CE: U2.16 U5.5 | length 11.6
  Top Layer w0.25: U5.5 -11.167,-14.815 -9.6,-16.382 U2.16
T-I/O: U2.17 U5.6 | length 13.9
  Top Layer w0.25: U5.6 -15.315,-16.085 -14.9,-16.5 -10.632,-16.5 -10.25,-16.882 U2.17
T-SCLK: U2.18 U5.7 | length 15.5
  Top Layer w0.25: U5.7 -16.585,-16.415 -15.618,-17.382 U2.18
TM-DATA: R7.2 TM.1 U2.13 | length 61.2
  Top Layer w0.25: v2(-9.45,-10.3) -8.85,-10.9 -8.35,-10.9 -4.368,-14.882 U2.13
  Top Layer w0.3: TM.1 -21.681,27.931 -20.65,26.9 -16.9,26.9 v2(-16.25,26.25) ; R7.2 -10.025,-10.875 v2(-9.45,-10.3)
  Bottom Layer w0.3: v2(-16.25,26.25) -15.55,25.55 -15.55,23.8 -12.8,21.05 -12.8,8.35 -10.25,5.8 -10.25,-9.5 v2(-9.45,-10.3)
TM-LED+: TM.2 U2.15 | length 57
  Top Layer w0.25: v2(-10.85,-12.05) -9.75,-13.15 -8.4,-13.15 -5.668,-15.882 U2.15
  Top Layer w0.3: v1(-19.681,28.831) TM.2
  Bottom Layer w0.3: v1(-19.681,28.831) -19.681,25.031 -14.45,19.8 -14.45,7.3 -11.9,4.75 -11.9,-11 v2(-10.85,-12.05)
TM-LED-: TM.3 U2.14 | length 55.1
  Top Layer w0.25: v2(-9.85,-11.6) -8.8,-11.6 -5.018,-15.382 U2.14
  Top Layer w0.3: v1(-17.691,28.821) TM.3
  Bottom Layer w0.3: v1(-17.691,28.821) -17.691,24.459 -13.6,20.368 -13.6,8 -11.05,5.45 -11.05,-10.4 v2(-9.85,-11.6)
VCC: C15.2 C18.2 C29.1 C30.2 CN3-1.1 JP1.1 LED1.A LED2.A LED3.A LED4.A LED5.A LED6.A pad.0 R1.2 R2.2 R5.1 R7.1 R8.2 U4.8 U5.8 U6.1 U6.6 | length 175.9
  Top Layer w0.3: v2(-19.1,-1.85) U6.6 ; U5.8 -17.855,-13.255 -16.775,-12.175 C29.1 ; U6.1 -17.05,5.1 v3(-16.75,4.8) -15.726,4.8 C18.2 ; C15.2@-17.065,8.041 C15.2
  Top Layer w0.4: C29.1 -15.75,-11.35 v2(-15.512,-11.112) -15.275,-10.875 R7.1 ; v3(-4.8,0) pad.0 ; v3(-2.1,-5.7) -1.45,-6.35 R5.1@-1.45,-6.765 ; R2.2 4.985,-7.465 6.984,-5.466 U4.8 10.295,-7.545 11.4,-8.65 15.45,-8.65 16.05,-9.25 C30.2 17.526,-10.474 17.995,-10.005 JP1.1 ; v3(17.25,9.3) 19,9.3 20.75,11.05 20.75,12.75 21.745,13.745 CN3-1.1 CN3-1.1@22.844,13.75
  Top Layer w0.5: C15.2@-17.065,8.041 R8.2 ; C15.2 -15.324,6.3 ; C18.2 -15.526,5.751 -14.977,6.3 -11.65,6.3 -9.5,4.15 -1.8,4.15 -0.5,2.85 v3(8.5,2.85) 9.2,2.85 9.735,3.385 R1.2
  Bottom Layer w0.3: v2(-19.1,-1.85) -18.15,-2.8 -16.75,-2.8 ; v3(-16.75,4.8) -16.75,-2.8 ; -15.512,-3.55 -16.262,-2.8 -16.75,-2.8
  Bottom Layer w0.4: v2(-15.512,-11.112) -15.512,-3.55 ; LED5.A -6.5,-5.7 ; LED1.A v2(-6.5,4.15) LED3.A ; v3(-4.8,0) LED3.A ; v3(-2.1,-5.7) -6.5,-5.7 ; LED6.A LED4.A v3(8.5,2.85) 8.5,9.3 ; LED2.A 8.5,9.3 ; v3(17.25,9.3) 8.5,9.3 ; -6.5,-5.7 LED3.A
  other v4: 8.5,-5.466
VDD: C5.2 C6.2 D1.1 D2.1 Q2.C R14.2 U1.0 U1.2 | length 64.2
  Top Layer w0.5: Q2.C -20.6,-7.601 -20.6,-5.05 -19.6,-4.05 R14.2 -18.885,-3.235 -17.15,-1.5 -16.05,-1.5 v4(-15.5,-0.95) ; v4(-13.65,2.1) -9.85,2.1 v3(-9.2,2.75) ; v4(-7.7,7.25) -0.35,7.25 1.55,9.15 U1.2 U1.0 1.01,16.178 D2.1 4.16,20.14 5.3,19 C5.2 7.96,21.3 12,21.3 12.736,20.564 14.01,20.564 D1.1
  Bottom Layer w0.5: v4(-15.5,-0.95) -14.95,-0.4 -14.95,0.8 v4(-13.65,2.1) ; v3(-9.2,2.75) -8.5,3.45 -8.5,6.45 v4(-7.7,7.25)
XERS: CN3-1.4 U2.5 | length 44.9
  Top Layer w0.25: U2.5 0.291,-9.659 0.7,-9.25 0.7,-6.3 4.7,-2.3 10.45,-2.3 12.05,-0.7 12.05,9.6 19.945,17.495 CN3-1.4
YY: U2.19 U3.3 | length 52.1
  Top Layer w0.25: v2(-12.025,-18.825) -9.575,-18.825 -8.632,-17.882 U2.19
  Top Layer w0.28: U3.3 -19.94,17.64 v2(-19.35,17.05)
  Bottom Layer w0.28: v2(-19.35,17.05) -18.8,16.5 -16.35,16.5 -15.8,15.95 -15.8,7.45 -12.8,4.45 -12.8,-18.05 v2(-12.025,-18.825)
pads on no net: ANT1.2 ANT1.3 ANT.2 CN1-1.3 CN1-1.4 CN2-1.4 CN2-1.5 CN3-1.7 CN3-1.8 JP3.3 JP3.4 JP4.3 JP4.4 SW.1 SW.2 SW.3 TM.5 TM.6 U2.4 U2.9 U3.1 U3.2 U3.8 U5.1 X2.0

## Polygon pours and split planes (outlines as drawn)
GND on Bottom Layer "01 Bottom Layer-No Net" (solid, remove dead copper, pour order 22): 3.9,-34.15 3.85,-34.15 -15.2,-34.15 -15.55,-34.5 -15.75,-34.7 -15.75,-35.6 -18.65,-35.6 -24.4,-41.35 -26.35,-43.3 -30.6,-43.3 -36.5,-43.3 -38.3,-41.5 -37.45,-40.65 -37.45,-20.75 -37.45,41.5 -36.3,42.65 -36.25,42.7 29.3,42.7 33.4,42.7 39,37.1 38.3,36.4 38.3,-43.5 27.65,-43.5 26.55,-44.6 20.4,-38.45 16.35,-38.45 8.3,-38.45 4.15,-34.3
GND on Top Layer "01 Bottom Layer-No Net" (solid, remove dead copper, pour order 24): 3.85,-34.15 -15.15,-34.15 -15.95,-34.95 -16.65,-35.65 -16.65,-42.6 -28.55,-42.6 -29.75,-43.8 -32.1,-41.45 -38.55,-41.45 -38.55,41 -36.9,42.65 -36.25,42 -7.45,42 35.35,42 38.25,39.1 38.9,38.45 38.9,-44.75 20.05,-44.75 19.9,-44.6 12.15,-36.85 7.9,-36.85 6.8,-36.85 6.2,-36.25

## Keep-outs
Keep-Out Layer:
  lines w0.2: -34.021,37.675 cw(c-31.526,37.509) -31.361,40.004 ; -34,-37.665 -34,-15 -26,-15 -26,-5 -34,-5 -34,37.805 ; -33.991,-37.215 ccw(c-31.508,-37.51) -31.804,-39.993 ; -31.821,-40.015 -27.601,-40.015 ; -31.571,40 -10,40 -10,35 10,35 10,40 31.519,40 ; -27.598,-40.008 ccw(c-27.57,-39.008) -26.571,-38.965 ; -26.575,-35.265 -26.564,-39.215 ; -26.573,-35.321 cw(c-25.58,-35.438) -25.463,-34.445 ; -25.561,-34.435 -16.141,-34.435 ; -16.181,-34.445 cw(c-16.11,-35.442) -15.113,-35.372 ; -15.101,-38.915 -15.101,-35.305 ; -15.101,-38.825 ccw(c-14.102,-38.779) -13.965,-39.769 ; -14.024,-39.785 2.333,-39.785 ; 2.359,-39.785 ccw(c2.279,-38.665) 3.399,-38.585 ; 3.392,-35.603 cw(c4.389,-35.532) 4.469,-34.535 ; 3.399,-38.815 3.399,-35.545 ; 4.499,-34.545 24.535,-34.565 ; 24.546,-34.565 cw(c24.534,-35.58) 25.549,-35.591 ; 25.529,-40.035 31.849,-40.035 ; 25.549,-39.965 25.549,-35.58 ; 31.359,39.995 cw(c31.509,37.5) 34.005,37.65 ; 31.841,-40.018 ccw(c31.537,-37.537) 34.037,-37.576 ; 34,-37.537 34,-15 26,-15 26,-5 34,-5 34,9 28,9 28,25 34,25 34,37.735

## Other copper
Top Layer:
  rectangle net GND: -0.065,-34.15 1.4,-33.55
  rectangle net GND: -0.5,-34.15 1.706,-33.2

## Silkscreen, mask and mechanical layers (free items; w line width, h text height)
Top Overlay:
  circle w0.2: c29.03,1.99 r1
  lines w0.2: -23.141,0.995 -21.631,0.995 -21.621,0.985 ; -22.321,0.035 -22.321,1.815 ; -0.351,23.435 1.439,23.435 1.449,23.445 ; 0.419,22.455 0.459,22.495 0.459,24.175 ; 15.689,27.905 17.899,27.905 17.909,27.915 ; 16.709,26.795 16.739,26.825 16.739,28.975 ; 17.109,12.265 20.249,12.265 20.309,12.205 ; 18.739,10.415 18.739,13.495
  text "BAT1" at 11.85,28 h1
  text "BAT" at -7.25,23.15 h1
  text "YY" at -29.1,21.6 h1
  text "VCC3.3" at -2.4,1.1 h1
  text "DJ" at -25.55,-3.9 h1
  text "VCC" at 21.529,-10.935 h0.8 r90
  text "GND" at 21.559,-13.695 h0.8 r90
  text "RST" at 21.559,-16.245 h0.8 r90
  text "DC" at 21.629,-18.265 h0.8 r90
  text "DD" at 21.659,-20.655 h0.8 r90
  text "2016/10/09" at 10.7,-30.9 h1.2
  text "BA100-CPU-V1.0" at 7.1,-33.75 h1.2
Mechanical 1:
  circle w0.2: c31,38 r1
  circle w0.2: c31,-37.5 r1
  circle w0.2: c-31,38 r1
  circle w0.2: c-31,-37.5 r1
  lines w0.2: -27.601,-40.015 -27.571,-39.985 ; -25.571,-34.445 -25.561,-34.435 ; 31.849,-40.035 31.899,-39.985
